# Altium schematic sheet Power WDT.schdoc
size 288 x 176 mm
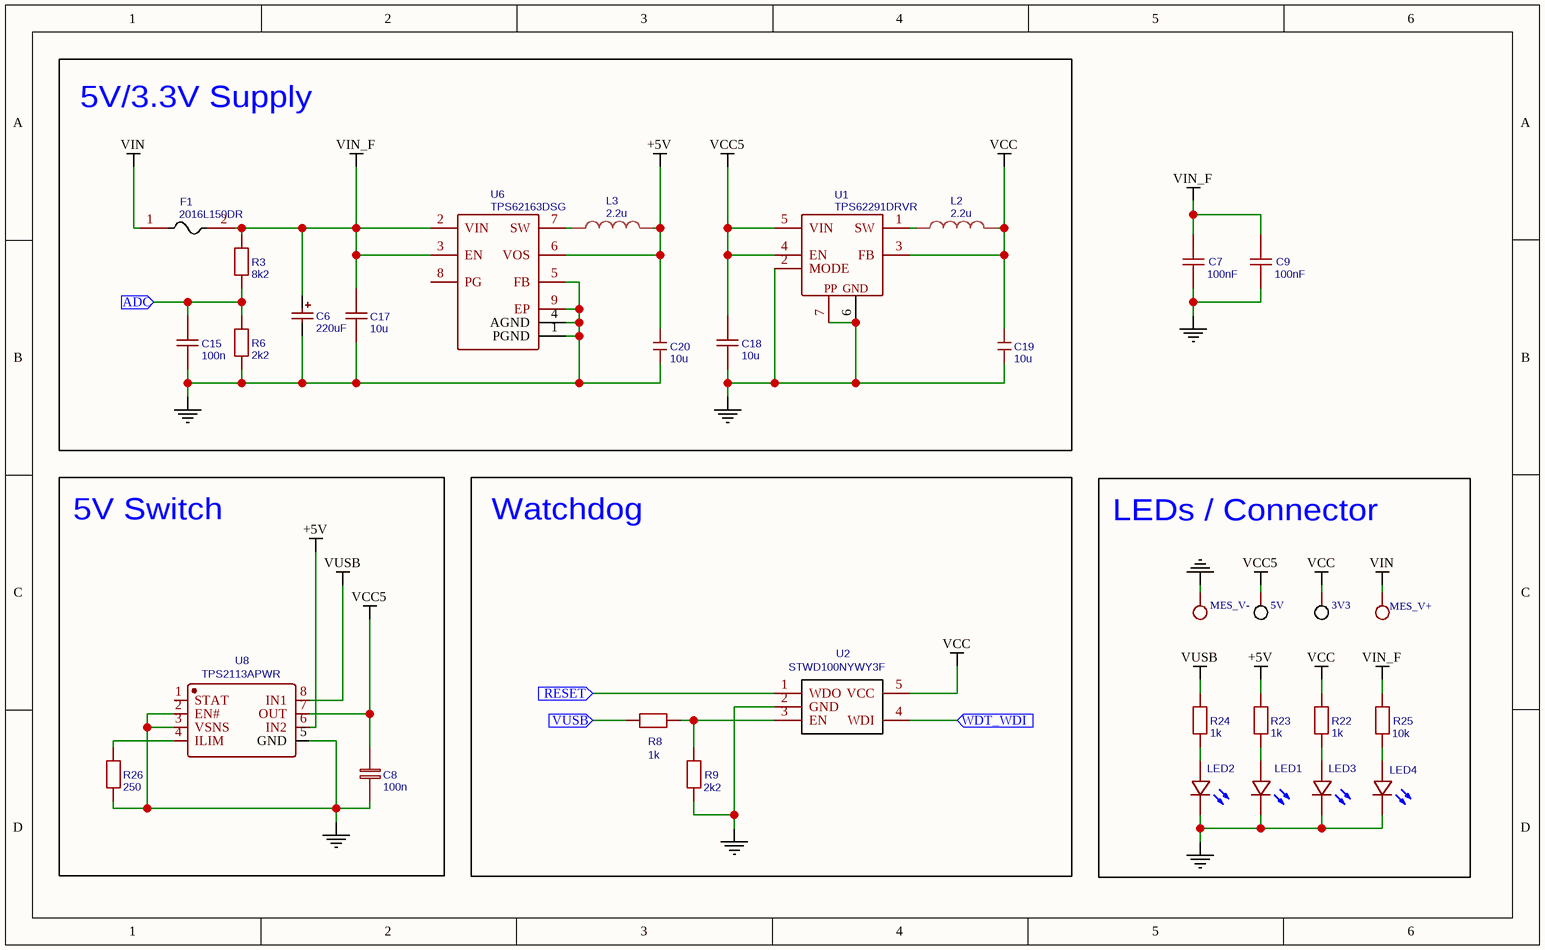
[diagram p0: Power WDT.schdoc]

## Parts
3V3  Pad  [PAD]  (value not drawn)
5V  Pad  [PAD]  (value not drawn)
C6  220uF  [CAP-SMD_L7.3-W4.3]
C7  100nF  [0603]
C8  100n  [0603]
C9  100nF  [0603]
C15  100n  [0603]
C17  10u  [0603]
C18  10u  [0603]
C19  10u  [0603]
C20  10u  [0603]
F1  2016L150DR  [F-SMD2016]
L2  2.2u  [LPS3015-223MRB]
L3  2.2u  [LPS3015-223MRB]
LED1  LED green  [LED-0603F]  (value not drawn)
LED2  LED blue  [LED-0603F]  (value not drawn)
LED3  LED red  [LED-0603F]  (value not drawn)
LED4  LED orange  [LED-0603F]  (value not drawn)
MES_V+  Pad  [PAD]  (value not drawn)
MES_V-  Y14  [PAD]  (value not drawn)
R3  8k2  [0603]
R6  2k2  [0603]
R8  1k  [0603]
R9  2k2  [0603]
R22  1k  [0603]
R23  1k  [0603]
R24  1k  [0603]
R25  10k  [0603]
R26  250  [0603]
U1  TPS62291DRVR  [SON-6-EP-2X2MM]
U2  STWD100NYWY3F  [SOT-23-5]
U6  TPS62163DSG  [WSON-8-PAD]
U8  TPS2113APWR  [TSSOP-8]

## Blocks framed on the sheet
5V/3.3V Supply: C6 C15 C17-C20 F1 L2 L3 R3 R6 U1 U6
5V Switch: C8 R26 U8
Watchdog: R8 R9 U2
LEDs / Connector: 3V3 5V LED1-LED4 MES_V+ MES_V- R22-R25

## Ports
ADC (in), RESET (in), VUSB (in), WDT_WDI (in)

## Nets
+5V: C20.2 L3.P$2 R23.2 U6.6(VOS) U8.6(IN2)
GND: C6.2 C7.1 C8.2 C9.1 C15.2 C17.2 C18.2 C19.1 C20.1 LED1.2(-) LED2.2(-) LED3.2(-) LED4.2(-) MES_V-.1 R6.1 R9.1 R26.2 U1.2(MODE) U1.6(GND) U1.7(EP) U2.2(GND) U6.1(PGND) U6.4(AGND) U6.5(FB) U6.9(EP) U8.2(EN#) U8.3(VSNS) U8.5(GND)
VCC: 3V3.1 C19.2 L2.P$2 R22.2 U1.3(FB) U2.5(VCC)
VCC5: 5V.1 C8.1 C18.1 U1.4(EN) U1.5(VIN) U8.7(OUT)
VIN: F1.1 MES_V+.1
VIN_F: C6.1 C7.2 C9.2 C17.1 F1.2 R3.2 R25.2 U6.2(VIN) U6.3(EN)
VUSB: R24.2 U8.8(IN1)
ADC: C15.1 R3.1 R6.2 ; port ADC
RESET: U2.1(WDO) ; port RESET
VUSB: R8.1 ; port VUSB  [a separate net that carries the same name]
WDT_WDI: U2.4(WDI) ; port WDT_WDI
NetL2_P$1: L2.P$1 U1.1(SW)
NetL3_P$1: L3.P$1 U6.7(SW)
NetLED1_1: LED1.1(+) R23.1
NetLED2_1: LED2.1(+) R24.1
NetLED3_1: LED3.1(+) R22.1
NetLED4_1: LED4.1(+) R25.1
NetR8_2: R8.2 R9.2 U2.3(EN)
NetR26_1: R26.1 U8.4(ILIM)

Not connected (* = marked no-connect by the designer): U6 8(PG); U8 1(STAT)

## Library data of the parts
C6 = 220uF: Manufacturer: AVX; Manufacturer Part: TAJE227K016RNJ; nameAlias: Capacitance; SMT Type: Extend
C7 C9 = 100nF: Manufacturer: YAGEO; Manufacturer Part: AC0603KRX7R9BB104; nameAlias: Capacitance; Contributor: LCSC
C8 C15 = 100n: Manufacturer Part: GRM188B11E104KA01D; Manufacturer: MuRata; nameAlias: Value(F)
C17 C18 = 10u: Manufacturer Part: GRM188R61C106MA73D; Manufacturer: MuRata; nameAlias: Value(F)
C19 C20 = 10u: Manufacturer Part: GRM188R61C106MA73D; Manufacturer: MuRata
F1 = 2016L150DR: Manufacturer: Littelfuse
L2 L3 = 2.2u: Manufacturer Part: VLS3015ET-2R2M; Manufacturer: TDK; Contributor: nrb1979
LED1 = LED green: Manufacturer: NATIONSTAR; Manufacturer Part: FC-1608GEK-572E
LED2 = LED blue: Manufacturer: NATIONSTAR; Manufacturer Part: FC-DA1608BK-470H10
LED3 = LED red: Manufacturer: NATIONSTAR; Manufacturer Part: FC-DA1608HRK-620D
LED4 = LED orange: Manufacturer: NATIONSTAR; Manufacturer Part: FC-1608GEK-572E
R3 = 8k2: Manufacturer Part: 0603WAF8201T5E; Manufacturer: UniOhm; nameAlias: Value(Ω)
R6 R9 = 2k2: Manufacturer Part: TC0325B2201T5E; Manufacturer: UniOhm; nameAlias: Value(Ω)
R8 R22-R24 = 1k: Manufacturer Part: 0603WAD1001T5E; Manufacturer: UniOhm; nameAlias: Value(Ω)
R25 = 10k: Manufacturer Part: RC0603JR-0710KL; Manufacturer: YAGEO; nameAlias: Value(Ω)
R26 = 250: Manufacturer Part: 0603WAJ0271T5E; Manufacturer: UniOhm; nameAlias: Value(Ω)
U1 = TPS62291DRVR: Manufacturer: TI; Contributor: LCSC
U2 = STWD100NYWY3F: Manufacturer: STMicroelectronics; SMT Type: Extend
U6 = TPS62163DSG: Manufacturer: TI
U8 = TPS2113APWR: Manufacturer: TI; Contributor: LCSC; SMT Type: Extend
